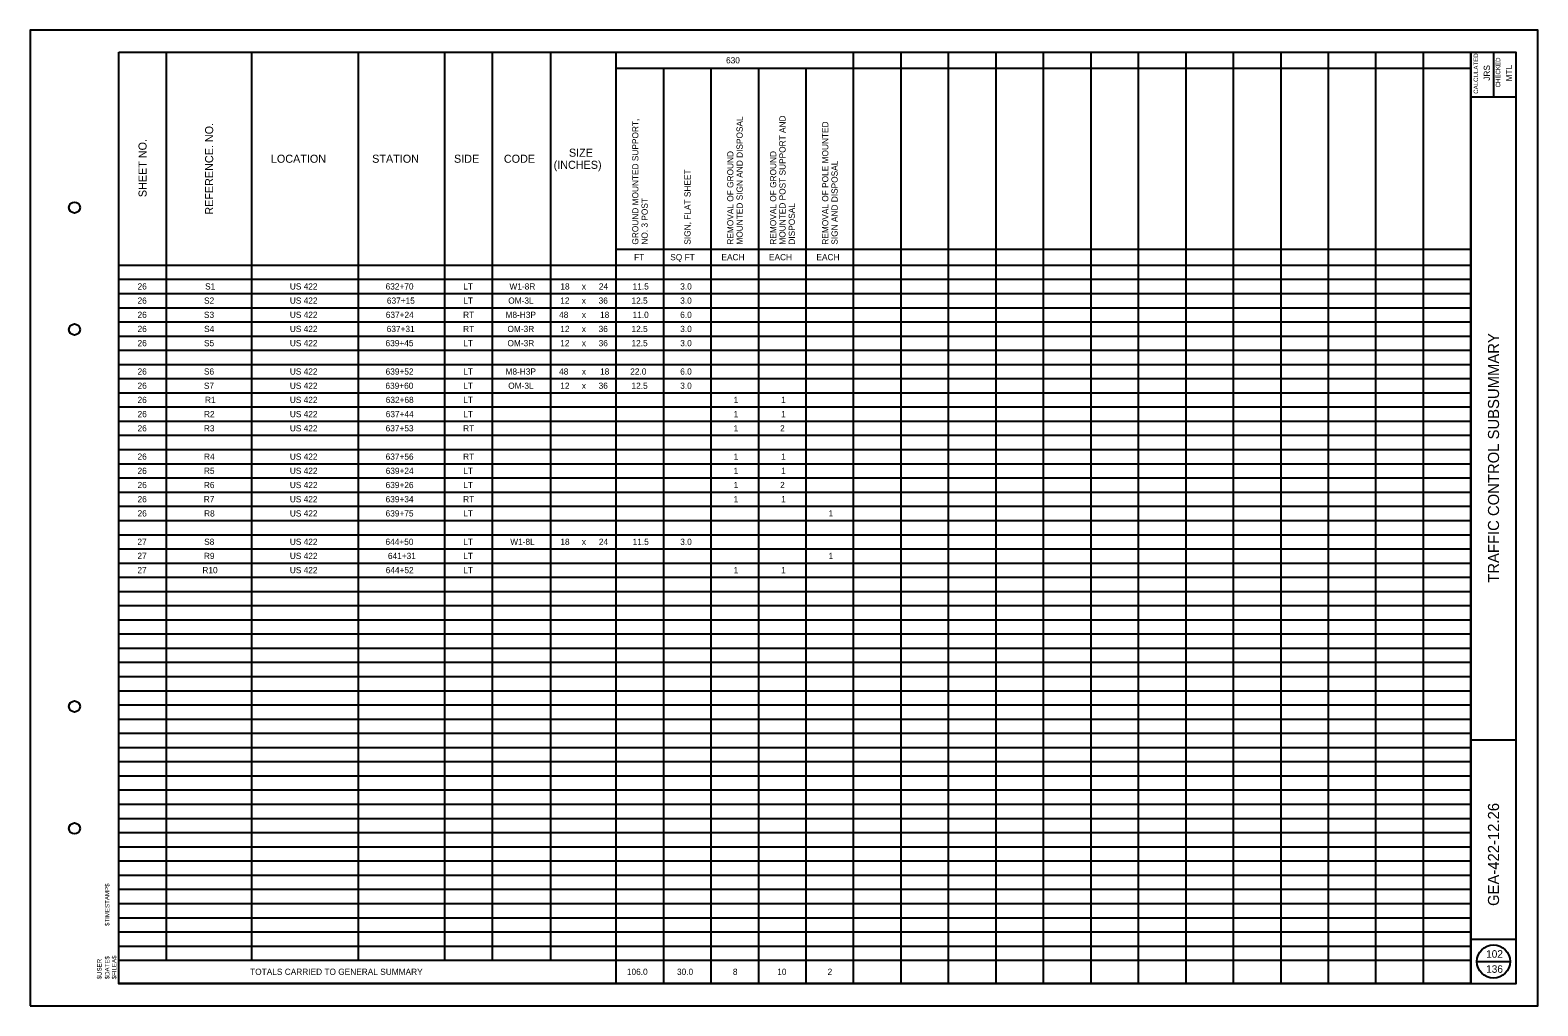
# Model space of a CAD drawing. Extents: x 0 to 34, y 0 to 22.
import ezdxf

# ---------------------------------------------------------------- set-up
doc = ezdxf.new("R2010")
doc.units = 0
for name, color, linetype in [('Default', 7, 'Continuous'), ('SH_Border', 7, 'Continuous'), ('SH_Cut_Line', 7, 'Continuous'), ('SH_Data', 7, 'Continuous'), ('SH_Text', 7, 'Continuous')]:
    doc.layers.add(name, color=color, linetype=linetype)

msp = doc.modelspace()

# ---------------------------------------------------------------- linework, layer by layer
at = {"layer": 'Default'}
msp.add_line((2, 21.5), (2, 21.5), dxfattribs=at)
at = {"layer": 'SH_Border'}
for p, q in [((2, 17.848), (2, 21.5)), ((32.5, 0.5), (32.5, 21.5)), ((33, 21.5), (33, 20.5)), ((32.5, 20.5), (33.5, 20.5)), ((32.5, 6), (33.5, 6)), ((32.5, 1.5), (33.5, 1.5))]:
    msp.add_line(p, q, dxfattribs=at)
msp.add_lwpolyline([(2, 21.5), (33.5, 21.5), (33.5, 0.5), (2, 0.5)], close=True, dxfattribs=at)
for centre in [(1, 18), (1, 15.25), (1, 6.75), (1, 4)]:
    msp.add_circle(centre, 0.125, dxfattribs=at)
at = {"layer": 'SH_Cut_Line'}
msp.add_lwpolyline([(0, 0), (34, 0), (34, 22), (0, 22)], close=True, dxfattribs=at)
at = {"layer": 'SH_Data'}
msp.add_line((32.625, 1), (33.375, 1), dxfattribs=at)
msp.add_circle((33, 1), 0.375, dxfattribs=at)
at = {"layer": 'SH_Text'}
for p, q in [((2, 21.5), (32.491, 21.5)), ((2, 0.509), (2, 21.5)), ((3.071, 1.028), (3.071, 21.5)), ((5.002, 1.028), (5.002, 21.5)), ((7.407, 1.028), (7.407, 21.5)), ((9.355, 1.028), (9.355, 21.5)), ((10.426, 1.028), (10.426, 21.5)), ((11.742, 1.028), (11.742, 21.5)), ((13.217, 0.509), (13.217, 21.5)), ((18.571, 0.509), (18.571, 21.5)), ((19.641, 0.509), (19.641, 21.5)), ((20.712, 0.509), (20.712, 21.5)), ((21.783, 0.509), (21.783, 21.5)), ((22.854, 0.509), (22.854, 21.5)), ((23.925, 0.509), (23.925, 21.5)), ((24.995, 0.509), (24.995, 21.5)), ((26.066, 0.509), (26.066, 21.5)), ((27.137, 0.509), (27.137, 21.5)), ((28.208, 0.509), (28.208, 21.5)), ((29.278, 0.509), (29.278, 21.5)), ((30.349, 0.509), (30.349, 21.5)), ((31.42, 0.509), (31.42, 21.5)), ((32.491, 0.509), (32.491, 21.5)), ((13.217, 21.14), (32.491, 21.14)), ((14.288, 0.509), (14.288, 21.14)), ((15.358, 0.509), (15.358, 21.14)), ((16.429, 0.509), (16.429, 21.14)), ((17.5, 0.509), (17.5, 21.14)), ((13.217, 17.062), (32.491, 17.062)), ((2, 16.702), (32.491, 16.702)), ((2, 16.382), (32.491, 16.382)), ((2, 16.062), (32.491, 16.062)), ((2, 15.742), (32.491, 15.742)), ((2, 15.422), (32.491, 15.422)), ((2, 15.103), (32.491, 15.103)), ((2, 14.783), (32.491, 14.783)), ((2, 14.463), (32.491, 14.463)), ((2, 14.143), (32.491, 14.143)), ((2, 13.823), (32.491, 13.823)), ((2, 13.503), (32.491, 13.503)), ((2, 13.183), (32.491, 13.183)), ((2, 12.864), (32.491, 12.864)), ((2, 12.544), (32.491, 12.544)), ((2, 12.224), (32.491, 12.224)), ((2, 11.904), (32.491, 11.904)), ((2, 11.584), (32.491, 11.584)), ((2, 11.264), (32.491, 11.264)), ((2, 10.944), (32.491, 10.944)), ((2, 10.624), (32.491, 10.624)), ((2, 10.305), (32.491, 10.305)), ((2, 9.985), (32.491, 9.985)), ((2, 9.665), (32.491, 9.665)), ((2, 9.345), (32.491, 9.345)), ((2, 9.025), (32.491, 9.025)), ((2, 8.705), (32.491, 8.705)), ((2, 8.385), (32.491, 8.385)), ((2, 8.065), (32.491, 8.065)), ((2, 7.746), (32.491, 7.746)), ((2, 7.426), (32.491, 7.426)), ((2, 7.106), (32.491, 7.106)), ((2, 6.786), (32.491, 6.786)), ((2, 6.466), (32.491, 6.466)), ((2, 6.146), (32.491, 6.146)), ((2, 5.826), (32.491, 5.826)), ((2, 5.506), (32.491, 5.506)), ((2, 5.187), (32.491, 5.187)), ((2, 4.867), (32.491, 4.867)), ((2, 4.547), (32.491, 4.547)), ((2, 4.227), (32.491, 4.227)), ((2, 3.907), (32.491, 3.907)), ((2, 3.587), (32.491, 3.587)), ((2, 3.267), (32.491, 3.267)), ((2, 2.948), (32.491, 2.948)), ((2, 2.628), (32.491, 2.628)), ((2, 2.308), (32.491, 2.308)), ((2, 1.988), (32.491, 1.988)), ((2, 1.668), (32.491, 1.668)), ((2, 1.348), (32.491, 1.348)), ((2, 1.028), (32.491, 1.028)), ((2, 0.509), (32.491, 0.509))]:
    msp.add_line(p, q, dxfattribs=at)

# ---------------------------------------------------------------- texts
at = {"layer": 'SH_Data'}
for s, height, rotation, p in [('CALCULATED', 0.1, 90, (32.652, 20.565)), ('JRS', 0.14, 90, (32.92, 20.859)), ('CHECKED', 0.1, 90, (33.152, 20.708)), ('MTL', 0.14, 90, (33.42, 20.844)), ('TRAFFIC CONTROL SUBSUMMARY', 0.25, 90, (33.125, 9.54)), ('GEA-422-12.26', 0.25, 90, (33.125, 2.252)), ('$TIMESTAMP$', 0.1, 89.9931, (1.788, 1.8)), ('$USER', 0.1, 89.9931, (1.611, 0.598)), ('$DATE$', 0.1, 89.9931, (1.788, 0.598)), ('$FILEA$', 0.1, 89.9931, (1.944, 0.598))]:
    msp.add_text(s, height=height, rotation=rotation, dxfattribs=at).set_placement(p)
for s, p in [('102', (32.833, 1.085)), ('136', (32.833, 0.745))]:
    msp.add_text(s, height=0.17, dxfattribs=at).set_placement(p)
at = {"layer": 'SH_Text'}
for s, height, p in [('630', 0.14, (15.693, 21.25)), ('LOCATION', 0.182, (5.429, 19.01)), ('STATION', 0.182, (7.713, 19.01)), ('SIDE', 0.182, (9.558, 19.01)), ('CODE', 0.182, (10.683, 19.01)), ('(INCHES)', 0.182, (11.805, 18.873)), ('SIZE', 0.182, (12.15, 19.146)), ('FT', 0.14, (13.62, 16.812)), ('SQ FT', 0.14, (14.435, 16.812)), ('EACH', 0.14, (15.59, 16.812)), ('EACH', 0.14, (16.661, 16.812)), ('EACH', 0.14, (17.732, 16.812)), ('26', 0.14, (2.422, 16.152)), ('S1', 0.14, (3.945, 16.152)), ('US 422', 0.14, (5.856, 16.152)), ('632+70', 0.14, (8.016, 16.152)), ('LT', 0.14, (9.768, 16.152)), ('W1-8R', 0.14, (10.809, 16.152)), ('18', 0.14, (11.957, 16.152)), ('x', 0.14, (12.441, 16.152)), ('24', 0.14, (12.825, 16.152)), ('11.5', 0.14, (13.587, 16.152)), ('3.0', 0.14, (14.66, 16.152)), ('26', 0.14, (2.422, 15.832)), ('26', 0.14, (2.422, 15.512)), ('S3', 0.14, (3.92, 15.512)), ('S2', 0.14, (3.922, 15.832)), ('US 422', 0.14, (5.856, 15.832)), ('US 422', 0.14, (5.856, 15.512)), ('637+24', 0.14, (8.02, 15.512)), ('637+15', 0.14, (8.045, 15.832)), ('RT', 0.14, (9.764, 15.512)), ('LT', 0.14, (9.768, 15.832)), ('M8-H3P', 0.14, (10.72, 15.512)), ('OM-3L', 0.14, (10.782, 15.832)), ('48', 0.14, (11.929, 15.512)), ('12', 0.14, (11.955, 15.832)), ('x', 0.14, (12.441, 15.832)), ('36', 0.14, (12.82, 15.832)), ('18', 0.14, (12.852, 15.512)), ('12.5', 0.14, (13.561, 15.832)), ('11.0', 0.14, (13.585, 15.512)), ('3.0', 0.14, (14.66, 15.832)), ('6.0', 0.14, (14.66, 15.512)), ('26', 0.14, (2.422, 15.193)), ('S4', 0.14, (3.923, 15.193)), ('US 422', 0.14, (5.856, 15.193)), ('637+31', 0.14, (8.041, 15.193)), ('RT', 0.14, (9.764, 15.193)), ('OM-3R', 0.14, (10.764, 15.193)), ('12', 0.14, (11.955, 15.193)), ('x', 0.14, (12.441, 15.512)), ('x', 0.14, (12.441, 15.193)), ('36', 0.14, (12.82, 15.193)), ('12.5', 0.14, (13.561, 15.193)), ('3.0', 0.14, (14.66, 15.193)), ('26', 0.14, (2.422, 14.873)), ('S5', 0.14, (3.921, 14.873)), ('US 422', 0.14, (5.856, 14.873)), ('639+45', 0.14, (8.015, 14.873)), ('LT', 0.14, (9.768, 14.873)), ('OM-3R', 0.14, (10.764, 14.873)), ('12', 0.14, (11.955, 14.873)), ('x', 0.14, (12.441, 14.873)), ('36', 0.14, (12.82, 14.873)), ('12.5', 0.14, (13.561, 14.873)), ('3.0', 0.14, (14.66, 14.873)), ('26', 0.14, (2.422, 14.233)), ('S6', 0.14, (3.92, 14.233)), ('US 422', 0.14, (5.856, 14.233)), ('639+52', 0.14, (8.016, 14.233)), ('LT', 0.14, (9.768, 14.233)), ('M8-H3P', 0.14, (10.72, 14.233)), ('48', 0.14, (11.929, 14.233)), ('x', 0.14, (12.441, 14.233)), ('18', 0.14, (12.852, 14.233)), ('22.0', 0.14, (13.532, 14.233)), ('6.0', 0.14, (14.66, 14.233)), ('26', 0.14, (2.422, 13.913)), ('S7', 0.14, (3.918, 13.913)), ('US 422', 0.14, (5.856, 13.913)), ('639+60', 0.14, (8.012, 13.913)), ('LT', 0.14, (9.768, 13.913)), ('OM-3L', 0.14, (10.782, 13.913)), ('12', 0.14, (11.955, 13.913)), ('x', 0.14, (12.441, 13.913)), ('36', 0.14, (12.82, 13.913)), ('12.5', 0.14, (13.561, 13.913)), ('3.0', 0.14, (14.66, 13.913)), ('26', 0.14, (2.422, 13.593)), ('R1', 0.14, (3.943, 13.593)), ('US 422', 0.14, (5.856, 13.593)), ('632+68', 0.14, (8.019, 13.593)), ('LT', 0.14, (9.768, 13.593)), ('1', 0.14, (15.865, 13.593)), ('1', 0.14, (16.935, 13.593)), ('26', 0.14, (2.422, 13.273)), ('R2', 0.14, (3.92, 13.273)), ('US 422', 0.14, (5.856, 13.273)), ('637+44', 0.14, (8.019, 13.273)), ('LT', 0.14, (9.768, 13.273)), ('1', 0.14, (15.865, 13.273)), ('1', 0.14, (16.935, 13.273)), ('26', 0.14, (2.422, 12.953)), ('R3', 0.14, (3.918, 12.953)), ('US 422', 0.14, (5.856, 12.953)), ('637+53', 0.14, (8.017, 12.953)), ('RT', 0.14, (9.764, 12.953)), ('1', 0.14, (15.865, 12.953)), ('2', 0.14, (16.912, 12.953)), ('26', 0.14, (2.422, 12.314)), ('R4', 0.14, (3.92, 12.314)), ('US 422', 0.14, (5.856, 12.314)), ('637+56', 0.14, (8.017, 12.314)), ('RT', 0.14, (9.764, 12.314)), ('1', 0.14, (15.865, 12.314)), ('1', 0.14, (16.935, 12.314)), ('26', 0.14, (2.422, 11.994)), ('R5', 0.14, (3.919, 11.994)), ('US 422', 0.14, (5.856, 11.994)), ('639+24', 0.14, (8.018, 11.994)), ('LT', 0.14, (9.768, 11.994)), ('1', 0.14, (15.865, 11.994)), ('1', 0.14, (16.935, 11.994)), ('26', 0.14, (2.422, 11.674)), ('R6', 0.14, (3.918, 11.674)), ('US 422', 0.14, (5.856, 11.674)), ('639+26', 0.14, (8.016, 11.674)), ('LT', 0.14, (9.768, 11.674)), ('1', 0.14, (15.865, 11.674)), ('2', 0.14, (16.912, 11.674)), ('26', 0.14, (2.422, 11.354)), ('R7', 0.14, (3.916, 11.354)), ('US 422', 0.14, (5.856, 11.354)), ('639+34', 0.14, (8.016, 11.354)), ('RT', 0.14, (9.764, 11.354)), ('1', 0.14, (15.865, 11.354)), ('1', 0.14, (16.935, 11.354)), ('26', 0.14, (2.422, 11.034)), ('R8', 0.14, (3.922, 11.034)), ('US 422', 0.14, (5.856, 11.034)), ('639+75', 0.14, (8.016, 11.034)), ('LT', 0.14, (9.768, 11.034)), ('1', 0.14, (18.006, 11.034)), ('27', 0.14, (2.419, 10.394)), ('27', 0.14, (2.419, 10.075)), ('S8', 0.14, (3.924, 10.394)), ('R9', 0.14, (3.919, 10.075)), ('US 422', 0.14, (5.856, 10.394)), ('US 422', 0.14, (5.856, 10.075)), ('644+50', 0.14, (8.014, 10.394)), ('641+31', 0.14, (8.068, 10.075)), ('LT', 0.14, (9.768, 10.394)), ('LT', 0.14, (9.768, 10.075)), ('W1-8L', 0.14, (10.827, 10.394)), ('18', 0.14, (11.957, 10.394)), ('x', 0.14, (12.441, 10.394)), ('24', 0.14, (12.825, 10.394)), ('11.5', 0.14, (13.587, 10.394)), ('3.0', 0.14, (14.66, 10.394)), ('1', 0.14, (18.006, 10.075)), ('27', 0.14, (2.419, 9.755)), ('R10', 0.14, (3.884, 9.755)), ('US 422', 0.14, (5.856, 9.755)), ('644+52', 0.14, (8.018, 9.755)), ('LT', 0.14, (9.768, 9.755)), ('1', 0.14, (15.865, 9.755)), ('1', 0.14, (16.935, 9.755)), ('TOTALS CARRIED TO GENERAL SUMMARY', 0.14, (4.961, 0.698)), ('106.0', 0.14, (13.457, 0.698)), ('30.0', 0.14, (14.587, 0.698)), ('8', 0.14, (15.847, 0.698)), ('10', 0.14, (16.847, 0.698)), ('2', 0.14, (17.983, 0.698))]:
    msp.add_text(s, height=height, dxfattribs=at).set_placement(p)
for s, height, p in [('MOUNTED POST SUPPORT AND', 0.14, (17.035, 17.164)), ('REFERENCE. NO.', 0.182, (4.127, 17.839)), ('GROUND MOUNTED SUPPORT,', 0.14, (13.717, 17.164)), ('MOUNTED SIGN AND DISPOSAL', 0.14, (16.069, 17.164)), ('REMOVAL OF POLE MOUNTED', 0.14, (18, 17.164)), ('SHEET NO.', 0.182, (2.626, 18.234)), ('REMOVAL OF GROUND', 0.14, (15.859, 17.164)), ('REMOVAL OF GROUND', 0.14, (16.825, 17.164)), ('SIGN AND DISPOSAL', 0.14, (18.21, 17.164)), ('SIGN, FLAT SHEET', 0.14, (14.893, 17.164)), ('NO. 3 POST', 0.14, (13.927, 17.164)), ('DISPOSAL', 0.14, (17.245, 17.164))]:
    msp.add_text(s, height=height, rotation=90, dxfattribs=at).set_placement(p)

doc.saveas('drawing.dxf')
